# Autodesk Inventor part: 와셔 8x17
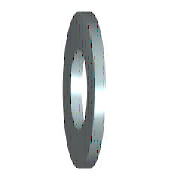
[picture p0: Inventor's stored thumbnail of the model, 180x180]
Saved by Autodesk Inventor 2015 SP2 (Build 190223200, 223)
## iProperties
IsCustomPart: 1
Created: 2012-02
Part Number: 와셔 8x17
Material: 강철, 연강
Description: 평면 와셔
Document SubType Name: Modeling
Standard: KS B 1326
Designer: mduedu
Standards Organization: KS
Language: ko-KR
Size Designation: 8x17
Categories: <MemberInstance><Categories><Category DisplayName="조임쇠" InternalName="e4da775c-781d-43d5-af7c-5136215cf5a6" Mnemonic="FSTN"><Category DisplayName="와셔" InternalN
Density: 1 g/cm^3
Appearance: 주황색
Author: mduedu
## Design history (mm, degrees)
sketch "스케치"
  geometry: C1 r 8.5 at (0, 0); C2 r 4.2 at (0, 0); 1 further point
  constraints: 2 centre point, 2 coincident
  dimensions: "d0" = 8.4 diameter of C2 (= SD1); "d1" = 17 diameter of C1 (= SD2)
extrude "본체" new body sketch "스케치" distance "d2" = 1.6 (= SD); taper "d3" = 0 deg
workaxis "Work Axis1"
workplane "Work Plane1"
body "Solid1"
other parameters: "SD1" = 8.4 [user parameter; used in 1 equation term], "SD2" = 17 [user parameter; used in 1 equation term], "SD" = 1.6 [user parameter; used in 1 equation term], "d4" = 0, "d5" = 0, "d6" = 0, "d7" = 0, "NND" = 8 [user parameter]
